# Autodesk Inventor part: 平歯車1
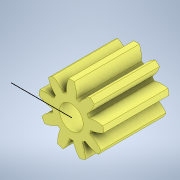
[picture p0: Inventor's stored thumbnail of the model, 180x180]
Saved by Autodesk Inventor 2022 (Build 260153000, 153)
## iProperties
CustomPartVersion: 1
Created: 2024-12
Part Number: 平歯車1
Material: Steel
Document SubType Name: Modeling
Designer: jsat7
Categories: <?xml version="1.0" encoding="UTF-16"?> <MemberInstance><Categories><FamilyTemplate><FamilyTemplateParameter ValueType="xs:double" Id="1" ObjectReferenceKey="da
Density: 1 g/cm^3
Appearance: Steel
Author: jsat7
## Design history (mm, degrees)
sketch "Sketch1"
  geometry: C1 r 2.75 at (0, 0)
  constraints: 1 centre point
  dimensions: "d0" = 5.5 diameter of C1 (= da_da)
extrude "Extrusion1" new body sketch "Sketch1" distance "d1" = 5.5 (= da_b); taper "d2" = 0 deg
workplane "Work Plane2"
sketch "Sketch2"
  geometry: C1 r 2.75 at (0, 0) reference; C2 r 2.25 at (0, 0)
  constraints: 1 centre point, 1 coincident
  dimensions: "d3" = 4.5 diameter of C2 (= da_d)
feature "ピッチ円直径" sketch "Sketch2" dims "d4" = 10, "d5" = 0
workplane "Work Plane8"
workplane "Work Plane9"
feature "平歯車" dims "da_b" = 5.5, "da_d" = 4.5, "da_aw" = 12, "da_da" = 5.5, "da_df" = 3.25, "da_dw" = 4.5, angle "da_beta" = 0 deg, "da_lefttooth" = 0, "da_righttooth" = 0
sketch "スケッチ3"
  geometry: C1 r 1 at (0, 0); 1 further point
  constraints: 1 centre point, 1 coincident
  dimensions: "d49" = 2 diameter of C1
extrude "押し出し2" cut sketch "スケッチ3" distance "d50" = 10; taper "d51" = 0 deg
sketch "スケッチ4"
  geometry: L1 (0, 0)-(-5.094, 0)
  constraints: 2 end point, 1 horizontal
body "Solid1"
body "Srf1"
other parameters: "d16" = 12 (= da_aw), "d17" = 0, "d34" = 20 deg (computed from da_z), "d39" = 0, "d41" = 0, "d43" = 12 (= da_aw), "d46" = 12 (= da_aw), "d47" = 0, "d48" = 0
